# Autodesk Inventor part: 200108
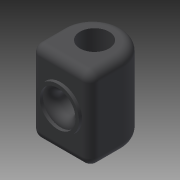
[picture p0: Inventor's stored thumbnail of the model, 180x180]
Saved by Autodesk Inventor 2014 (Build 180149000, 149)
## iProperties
Created: 2007-10
Part Number: 200108
Document SubType Name: Modeling
Designer: TH
Density: 1.32 g/cm^3
Mass: 29.3271 g
Surface Area: 68.098 cm^2
Volume: 22.2175 cm^3
Material: Polyaryletherketone Resin
Description: BALL SCREW MOUNTING BLOCK
Appearance: Gray
Component Category: Lower Component
Author: TH
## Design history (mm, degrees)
sketch "Sketch1"
  geometry: L1 (0, 39.033)-(0, -6.505) reference; L2 (-545.088, 0)-(239.688, 0) reference; L3 (-14.25, 0)-(14.25, 0); L4 (14.25, 0)-(14.25, 15.326); L5 (0, 29.576)-(0, 29.576); L6 (-14.25, 15.326)-(-14.25, 0); L7 (-432.977, 16.217)-(127.577, 16.217) reference; C1 r 7 at (0, 16.217); A1 r 14.25 centre (0, 15.326) between (0, 29.576) and (-14.25, 15.326); A2 r 14.25 centre (0, 15.326) between (14.25, 15.326) and (0, 29.576); 2 further points
  constraints: 10 end point, 5 point on line, 4 point on circle, 4 tangent, 3 centre point, 2 horizontal, 2 parallel, 1 concentric, 1 perpendicular, 2 other
  dimensions: "d0" = 28.5 distance of L3.start L3.end; "d1" = 14.25 distance between parallel lines of L6 L1 (= 0.5 x d0); "d2" = 29.576 distance of point (-14.25, 29.576) L3.start; "d3" = 14.25 radius of A1; "d4" = 14 diameter of C1
extrude "Extrusion1" new body sketch "Sketch1" stored distance "d6" = 39.4; taper "d7" = 0 deg
fillet "Fillet1" dims "d8" = 4
sketch "Sketch2"
  geometry: C1 r 4.6 at (10.25, -15.7); 1 further point
  constraints: 1 centre point, 1 coincident
  dimensions: "d9" = 9.2 diameter of C1
extrude "Extrusion2" cut sketch "Sketch2" stored distance "d10" = 39.4; taper "d11" = 0 deg
fillet "Fillet2" dims "d12" = 4
sketch "Sketch3"
  geometry: L1 (20.5, 0)-(20.5, -31.4) reference; C1 r 8.6 at (10.25, -15.7) reference; C2 r 10.25 at (10.25, -15.7); C3 r 8.6 at (10.25, -15.7)
  constraints: 2 centre point, 2 coincident, 1 concentric, 1 tangent
extrude "Extrusion3" join sketch "Sketch3" distance "d13" = 1.5; taper "d14" = 0 deg
body "Solid1"
